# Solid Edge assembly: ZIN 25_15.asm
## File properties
Title: Zylinder
Author: bmolnar
Template: iso metric assembly.asm
Last saved by: bmolnar
Revision: 10
Application: Solid Edge
Username: bmolnar
Dokumentum tartalom típus: 1
Document Number: ZIN 25/15
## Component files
Kit_1.par
Kit_2.par
Profilrohr.par
Kolbenstange.par
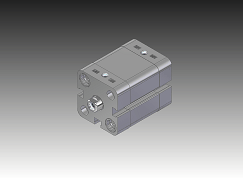
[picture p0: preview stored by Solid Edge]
